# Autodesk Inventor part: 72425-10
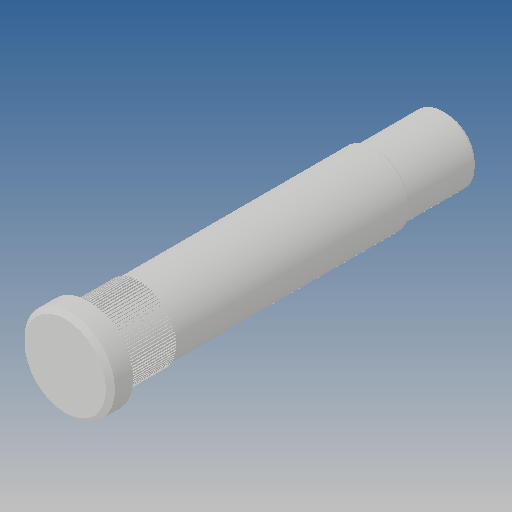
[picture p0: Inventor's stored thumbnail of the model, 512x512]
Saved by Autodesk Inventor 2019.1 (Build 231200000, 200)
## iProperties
Created: 2012-10
Part Number: 72425-10
Material: Ogólny
Document SubType Name: Modeling
Designer: CADENGINEERING4
Density: 1 g/cm^3
Appearance: Domyślna
Author: CADENGINEERING4
Revision Number: ÈÎºÎ
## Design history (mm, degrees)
feature "ÊäÈë1"
node "Bryła1"
